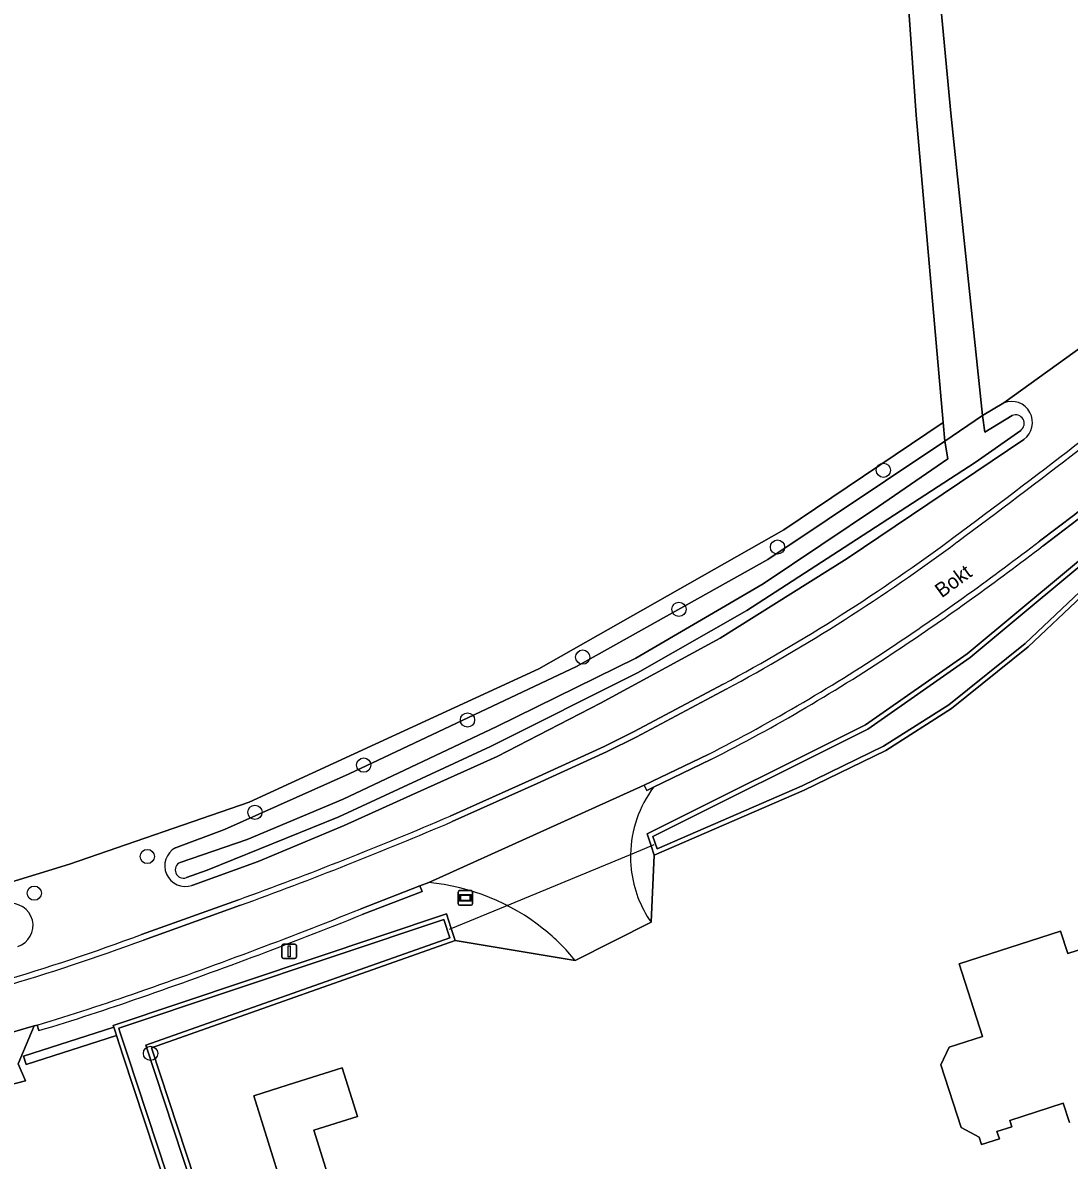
# Model space of a CAD drawing. Extents: x 162510 to 163918, y 388494 to 389774.
# Drawn here: x 163197 to 163268.7, y 388980.1 to 389058.1 of the extents above; entities that cross this region are included whole.
import ezdxf

# ---------------------------------------------------------------- set-up
doc = ezdxf.new("R2010")
doc.units = 0
for name, color, linetype in [('IMGEO_Boom', 7, 'Continuous'), ('IMGEO_Bouwland', 7, 'Continuous'), ('IMGEO_Duiker', 7, 'Continuous'), ('IMGEO_Erf', 7, 'Continuous'), ('IMGEO_Grasland_overig', 7, 'Continuous'), ('IMGEO_Groenvoorziening', 7, 'Continuous'), ('IMGEO_Haag', 7, 'Continuous'), ('IMGEO_Lichtmast', 7, 'Continuous'), ('IMGEO_Loofbos', 7, 'Continuous'), ('IMGEO_Oever', 7, 'Continuous'), ('IMGEO_Openbare_ruimte_label', 7, 'Continuous'), ('IMGEO_Pand', 7, 'Continuous'), ('IMGEO_Rijbaan_lokaal_gesloten', 7, 'Continuous'), ('IMGEO_Rijbaan_lokaal_halfverhard', 7, 'Continuous'), ('IMGEO_Rijbaan_lokaal_open', 7, 'Continuous'), ('IMGEO_Verklikker', 7, 'Continuous'), ('IMGEO_Waterloop', 7, 'Continuous')]:
    doc.layers.add(name, color=color, linetype=linetype)

msp = doc.modelspace()

# ---------------------------------------------------------------- linework, layer by layer
at = {"layer": 'IMGEO_Boom'}
for centre in [(163255.98, 389027.4), (163248.726, 389022.14), (163241.972, 389017.875), (163235.38, 389014.6), (163227.484, 389010.295), (163220.374, 389007.204), (163212.919, 389003.971), (163205.542, 389000.942), (163197.799, 388998.433), (163205.769, 388987.457)]:
    msp.add_circle(centre, 0.489, dxfattribs=at)
at = {"layer": 'IMGEO_Bouwland'}
msp.add_lwpolyline([(163255.473, 389089.062), (163223.18, 389081.542), (163199.482, 389075.574), (163185.761, 389072.18), (163174.689, 389069.454), (163173.678, 389061.095), (163170.279, 389025.019), (163167.954, 388999.891), (163167.603, 388990.424), (163200.207, 389000.418), (163212.52, 389004.669), (163232.363, 389013.797), (163249.165, 389023.322), (163260.08, 389030.662), (163258.23, 389051.717), (163256.486, 389076.515)], close=True, dxfattribs=at)
at = {"layer": 'IMGEO_Duiker'}
msp.add_lwpolyline([(163226.241, 388995.959), (163226.37, 388996.013), (163230.094, 388997.552), (163238.653, 389001.09), (163240.064, 389001.673), (163240.284, 389001.764)], dxfattribs=at)
at = {"layer": 'IMGEO_Erf'}
for points in [[(163299.678, 389102.603), (163257.727, 389091.219), (163256.916, 389090.999), (163260.609, 389051.86), (163262.76, 389031.156), (163264.225, 389032.019), (163270.263, 389036.355), (163270.353, 389036.42), (163278.738, 389042.731), (163291.024, 389052.399), (163296.992, 389058.187), (163298.476, 389059.845), (163301.365, 389063.917), (163302.714, 389067.144), (163304.217, 389072.884), (163304.823, 389078.805), (163304.577, 389084.736), (163303.423, 389090.573)], [(163219.946, 388983.139), (163216.953, 388982.202), (163217.888, 388979.215), (163214.814, 388978.252), (163212.839, 388984.559), (163215.202, 388985.299), (163218.906, 388986.459)]]:
    msp.add_lwpolyline(points, close=True, dxfattribs=at)
for points in [[(163296.588, 388975.913), (163313.192, 388984.698), (163306.1, 389006.712), (163301.392, 389010.474), (163291.734, 389007.828), (163284.723, 389009.283), (163280.491, 389028.19), (163273.806, 389023.406), (163273.26, 389022.236), (163265.908, 389015.299), (163260.651, 389011.077), (163256.153, 389008.214), (163250.555, 389005.491), (163240.278, 389001.025), (163240.061, 388996.438), (163234.852, 388993.823), (163226.643, 388995.178), (163205.829, 388987.826), (163237.905, 388890.433)], [(163224.824, 388999.162), (163224.221, 388998.928), (163224.371, 388998.557), (163220.275, 388996.969)], [(163203.899, 388987.269), (163203.43, 388988.692), (163197.255, 388986.687), (163197.07, 388987.257), (163203.242, 388989.262), (163203.208, 388989.364), (163226.042, 388997.017), (163226.37, 388996.013), (163226.643, 388995.178), (163234.852, 388993.823)], [(163268.736, 388982.712), (163268.304, 388984.049), (163264.636, 388982.863), (163264.774, 388982.435), (163263.763, 388982.108), (163263.924, 388981.611), (163262.705, 388981.217), (163262.545, 388981.714), (163261.306, 388982.375), (163259.917, 388986.672), (163260.494, 388987.873), (163262.778, 388988.611), (163261.172, 388993.581), (163268.119, 388995.826), (163268.615, 388994.295), (163272.079, 388995.415)], [(163198.123, 388989.019), (163198.002, 388989.4), (163197.788, 388989.336), (163196.707, 388986.733), (163197.209, 388985.575), (163193.741, 388984.697), (163193.48, 388985.337), (163190.473, 388987.347), (163190.578, 388986.979), (163187.117, 388986.029), (163182.303, 388984.673), (163178.332, 388983.566)], [(163220.028, 388938.344), (163203.899, 388987.269)]]:
    msp.add_lwpolyline(points, dxfattribs=at)
for centre, radius, start, end in [((163223.437, 388984.431), 14.796, 51.26004, 84.62106), ((163091.453, 389317.943), 345.861, 289.18456, 291.86791), ((163224.807, 388985.901), 12.793, 38.26036, 51.92597), ((163152.686, 389140.624), 158.268, 286.68362, 289.34251)]:
    msp.add_arc(centre, radius, start, end, dxfattribs=at)
at = {"layer": 'IMGEO_Grasland_overig'}
for points in [[(163261.728, 389014.837), (163272.067, 389023.432), (163272.685, 389022.812), (163273.26, 389022.236), (163273.806, 389023.406), (163273.582, 389023.532), (163270.321, 389025.372), (163270.16, 389025.245), (163270.413, 389024.935), (163269.328, 389024.048), (163266.93, 389022.235)], [(163240.061, 388996.438), (163240.278, 389001.025), (163240.064, 389001.673), (163239.797, 389002.485), (163254.752, 389009.953), (163261.728, 389014.837)], [(163244.158, 389007.578), (163240.235, 389005.688)]]:
    msp.add_lwpolyline(points, dxfattribs=at)
for centre, radius, start, end in [((163154.852, 389168.069), 183.926, 303.72551, 307.54335), ((163187.132, 389119.446), 125.564, 297.01082, 303.79355), ((163246.556, 389000.942), 7.904, 143.09895, 178.92819), ((163246.487, 389000.946), 7.836, 178.94748, 186.93463), ((163246.519, 389000.927), 7.865, 186.76714, 214.80258)]:
    msp.add_arc(centre, radius, start, end, dxfattribs=at)
at = {"layer": 'IMGEO_Groenvoorziening'}
msp.add_lwpolyline([(163203.43, 388988.692), (163203.361, 388988.9), (163203.242, 388989.262), (163197.07, 388987.257), (163197.255, 388986.687)], close=True, dxfattribs=at)
at = {"layer": 'IMGEO_Haag'}
msp.add_lwpolyline([(163203.43, 388988.692), (163203.361, 388988.9), (163203.242, 388989.262), (163197.07, 388987.257), (163197.255, 388986.687)], close=True, dxfattribs=at)
at = {"layer": 'IMGEO_Lichtmast'}
for p, q in [((163214.771, 388994.046), (163214.771, 388994.846)), ((163214.771, 388994.846), (163214.771, 388994.046)), ((163214.871, 388994.946), (163215.661, 388994.946)), ((163215.661, 388994.946), (163214.871, 388994.946)), ((163215.761, 388994.846), (163215.761, 388994.046)), ((163215.761, 388994.046), (163215.761, 388994.846)), ((163215.661, 388993.946), (163214.871, 388993.946)), ((163214.871, 388993.946), (163215.661, 388993.946))]:
    msp.add_line(p, q, dxfattribs=at)
msp.add_lwpolyline([(163215.191, 388994.821), (163215.341, 388994.821), (163215.341, 388994.071), (163215.191, 388994.071), (163215.191, 388994.821)], dxfattribs=at)
for centre, start, end in [((163214.871, 388994.846), 90, 180), ((163214.871, 388994.846), 90, 180), ((163215.661, 388994.846), 0, 90), ((163215.661, 388994.846), 360, 90), ((163214.871, 388994.046), 180, 270), ((163214.871, 388994.046), 180, 270), ((163215.661, 388994.046), 270, 0), ((163215.661, 388994.046), 270, 0)]:
    msp.add_arc(centre, 0.1, start, end, dxfattribs=at)
at = {"layer": 'IMGEO_Loofbos'}
for points in [[(163270.263, 389036.355), (163264.225, 389032.019)], [(163207.472, 389001.54), (163210.831, 389002.803), (163219.379, 389006.613), (163221.365, 389007.536), (163234.95, 389013.954), (163248.066, 389021.285), (163260.197, 389029.398), (163260.08, 389030.662), (163249.165, 389023.322), (163232.363, 389013.797), (163212.52, 389004.669), (163200.207, 389000.418), (163167.603, 388990.424), (163167.954, 388999.891), (163170.279, 389025.019)], [(163265.6, 389029.505), (163253.49, 389021.366), (163244.794, 389015.894), (163236.597, 389011.445), (163229.508, 389007.785), (163224.292, 389005.431), (163219.03, 389003.057), (163213.146, 389000.6), (163208.655, 388998.986), (163208.602, 388998.967)], [(163226.287, 389003.706), (163232.098, 389006.305), (163236.841, 389008.468), (163238.849, 389009.479), (163245.009, 389012.752)], [(163205.147, 388995.598), (163211.792, 388997.982)]]:
    msp.add_lwpolyline(points, dxfattribs=at)
for centre, radius, start, end in [((162908.133, 389497.572), 591.418, 306.606801, 308.623043), ((163264.753, 389030.675), 1.444, 305.89934, 111.45244), ((163184.86, 389124.633), 127.025, 298.2632, 306.71907), ((163115.529, 389262.965), 281.927, 289.96501, 293.1326), ((163208.151, 389000.304), 1.411, 118.79318, 288.62668), ((163196.213, 388996.224), 1.505, 287.39687, 100.75885), ((163153.78, 389134.015), 147.641, 286.37236, 290.35997)]:
    msp.add_arc(centre, radius, start, end, dxfattribs=at)
at = {"layer": 'IMGEO_Oever'}
for points in [[(163264.225, 389032.019), (163262.76, 389031.156), (163262.939, 389030.018), (163264.805, 389031.152)], [(163265.391, 389030.134), (163262.262, 389027.928), (163253.289, 389022.099), (163246.633, 389017.79), (163239.127, 389013.527), (163229.059, 389008.487), (163218.661, 389003.65), (163209.642, 389000), (163208.22, 388999.497)], [(163229.504, 389009.849), (163239.019, 389014.524), (163247.748, 389019.625), (163255.64, 389024.926), (163260.385, 389028.191), (163260.197, 389029.398), (163248.066, 389021.285), (163234.95, 389013.954), (163221.365, 389007.536), (163219.379, 389006.613), (163210.831, 389002.803), (163207.472, 389001.54)], [(163208.602, 388998.967), (163208.655, 388998.986), (163213.146, 389000.6), (163219.03, 389003.057), (163224.292, 389005.431), (163229.508, 389007.785), (163236.597, 389011.445), (163244.794, 389015.894), (163253.49, 389021.366), (163265.6, 389029.505)], [(163207.807, 389000.543), (163212.384, 389002.113), (163218.964, 389004.875), (163229.504, 389009.849)], [(163205.829, 388987.826), (163226.643, 388995.178), (163226.37, 388996.013), (163226.042, 388997.017), (163203.208, 388989.364), (163203.242, 388989.262), (163203.361, 388988.9), (163203.43, 388988.692), (163203.899, 388987.269), (163220.028, 388938.344), (163223.616, 388927.461), (163236.766, 388888.053), (163294.567, 388906.947), (163302.097, 388885.506), (163302.403, 388884.634), (163389.097, 388910.154)], [(163204.183, 388987.363), (163203.645, 388988.993), (163203.586, 388989.175), (163225.851, 388996.637), (163226.268, 388995.363), (163205.453, 388988.011), (163237.714, 388890.055), (163295.698, 388909.171), (163303.452, 388886.507), (163348.836, 388899.935), (163350.219, 388900.446), (163351.114, 388900.684), (163388.413, 388911.451), (163389.08, 388915.215), (163389.499, 388916.535)], [(163389.001, 388910.438), (163302.591, 388885.001), (163302.379, 388885.605), (163294.752, 388907.322), (163236.956, 388888.43), (163223.9, 388927.555), (163220.312, 388938.438), (163204.183, 388987.363)], [(163389.217, 388916.637), (163388.789, 388915.287), (163388.151, 388911.687), (163362.046, 388904.151), (163360.59, 388903.731), (163351.034, 388900.972), (163350.129, 388900.732), (163348.742, 388900.219), (163303.642, 388886.875), (163295.885, 388909.548), (163237.905, 388890.433), (163205.829, 388987.826)]]:
    msp.add_lwpolyline(points, dxfattribs=at)
for points in [[(163256.153, 389008.214), (163260.651, 389011.077), (163265.908, 389015.299), (163273.26, 389022.236), (163272.685, 389022.812), (163272.067, 389023.432), (163261.728, 389014.837), (163254.752, 389009.953), (163239.797, 389002.485), (163240.064, 389001.673), (163240.278, 389001.025), (163250.555, 389005.491)], [(163272.456, 389022.584), (163272.796, 389022.243), (163265.696, 389015.543), (163260.462, 389011.34), (163255.995, 389008.497), (163250.42, 389005.785), (163240.474, 389001.462), (163240.191, 389002.321), (163254.918, 389009.675), (163261.924, 389014.58), (163272.047, 389022.995)]]:
    msp.add_lwpolyline(points, close=True, dxfattribs=at)
for centre, radius, start, end in [((163264.753, 389030.675), 1.444, 305.89934, 111.45244), ((163265.034, 389030.606), 0.592, 307.04878, 112.804), ((163208.151, 389000.304), 1.411, 118.79318, 288.62668), ((163208.02, 389000.023), 0.562, 112.24936, 290.84257), ((163196.213, 388996.224), 1.505, 287.39687, 100.75885)]:
    msp.add_arc(centre, radius, start, end, dxfattribs=at)
at = {"layer": 'IMGEO_Pand'}
msp.add_lwpolyline([(163272.079, 388995.415), (163268.615, 388994.295), (163268.119, 388995.826), (163261.172, 388993.581), (163262.778, 388988.611), (163260.494, 388987.873), (163259.917, 388986.672), (163261.306, 388982.375), (163262.545, 388981.714), (163262.705, 388981.217), (163263.924, 388981.611), (163263.763, 388982.108), (163264.774, 388982.435), (163264.636, 388982.863), (163268.304, 388984.049), (163268.736, 388982.712)], dxfattribs=at)
msp.add_lwpolyline([(163212.839, 388984.559), (163214.814, 388978.252), (163217.888, 388979.215), (163216.953, 388982.202), (163219.946, 388983.139), (163218.906, 388986.459), (163215.202, 388985.299)], close=True, dxfattribs=at)
at = {"layer": 'IMGEO_Rijbaan_lokaal_gesloten'}
for points in [[(163266.686, 389022.552), (163269.087, 389024.367), (163270.16, 389025.245), (163270.321, 389025.372), (163280.513, 389033.412), (163285.735, 389037.648)], [(163245.197, 389012.399), (163239.029, 389009.122), (163237.007, 389008.104), (163232.261, 389005.94), (163226.444, 389003.338)], [(163220.126, 388997.34), (163224.221, 388998.928), (163224.824, 388999.162), (163239.596, 389005.824), (163243.976, 389007.934)], [(163240.235, 389005.688), (163239.77, 389005.464), (163239.596, 389005.824), (163224.824, 388999.162)], [(163211.927, 388997.605), (163205.286, 388995.223)], [(163234.852, 388993.823), (163240.061, 388996.438)], [(163178.219, 388983.931), (163182.23, 388985.017), (163187.003, 388986.355), (163190.473, 388987.347), (163191.057, 388987.377), (163197.788, 388989.336), (163198.002, 388989.4)]]:
    msp.add_lwpolyline(points, dxfattribs=at)
for centre, radius, start, end in [((162905.811, 389500.603), 595.636, 306.61225, 308.61552), ((163184.796, 389124.736), 127.546, 298.2657, 306.7141), ((163154.672, 389168.303), 183.822, 303.73151, 307.54322), ((163186.834, 389119.961), 125.759, 297.02495, 303.77589), ((163246.556, 389000.942), 7.904, 143.09895, 178.92819), ((163115.637, 389262.675), 282.018, 289.96418, 293.13557), ((163246.487, 389000.946), 7.836, 178.94748, 186.93463), ((163246.519, 389000.927), 7.865, 186.76714, 214.80258), ((163223.437, 388984.431), 14.796, 51.26004, 84.62106), ((163091.949, 389316.672), 344.097, 289.17646, 291.87013), ((163224.807, 388985.901), 12.793, 38.26036, 51.92597), ((163153.605, 389134.532), 148.586, 286.38228, 290.3539), ((163153.101, 389139.283), 156.464, 286.67686, 289.36304)]:
    msp.add_arc(centre, radius, start, end, dxfattribs=at)
at = {"layer": 'IMGEO_Rijbaan_lokaal_halfverhard'}
for points in [[(163270.16, 389025.245), (163269.087, 389024.367), (163266.686, 389022.552)], [(163266.93, 389022.235), (163269.328, 389024.048), (163270.413, 389024.935), (163270.16, 389025.245)], [(163245.009, 389012.752), (163238.849, 389009.479), (163236.841, 389008.468), (163232.098, 389006.305), (163226.287, 389003.706)], [(163226.444, 389003.338), (163232.261, 389005.94), (163237.007, 389008.104), (163239.029, 389009.122), (163245.197, 389012.399)], [(163243.976, 389007.934), (163239.596, 389005.824), (163239.77, 389005.464), (163240.235, 389005.688), (163244.158, 389007.578)], [(163224.221, 388998.928), (163220.126, 388997.34)], [(163220.275, 388996.969), (163224.371, 388998.557), (163224.221, 388998.928)], [(163211.792, 388997.982), (163205.147, 388995.598)], [(163205.286, 388995.223), (163211.927, 388997.605)], [(163198.002, 388989.4), (163198.123, 388989.019)]]:
    msp.add_lwpolyline(points, dxfattribs=at)
for centre, radius, start, end in [((162908.133, 389497.572), 591.418, 306.606801, 308.623043), ((162905.811, 389500.603), 595.636, 306.61225, 308.61552), ((163184.86, 389124.633), 127.025, 298.2632, 306.71907), ((163184.796, 389124.736), 127.546, 298.2657, 306.7141), ((163154.672, 389168.303), 183.822, 303.73151, 307.54322), ((163154.852, 389168.069), 183.926, 303.72551, 307.54335), ((163186.834, 389119.961), 125.759, 297.02495, 303.77589), ((163187.132, 389119.446), 125.564, 297.01082, 303.79355), ((163115.529, 389262.965), 281.927, 289.96501, 293.1326), ((163115.637, 389262.675), 282.018, 289.96418, 293.13557), ((163091.949, 389316.672), 344.097, 289.17646, 291.87013), ((163091.453, 389317.943), 345.861, 289.18456, 291.86791), ((163153.78, 389134.015), 147.641, 286.37236, 290.35997), ((163153.605, 389134.532), 148.586, 286.38228, 290.3539), ((163153.101, 389139.283), 156.464, 286.67686, 289.36304), ((163152.686, 389140.624), 158.268, 286.68362, 289.34251)]:
    msp.add_arc(centre, radius, start, end, dxfattribs=at)
at = {"layer": 'IMGEO_Rijbaan_lokaal_open'}
msp.add_lwpolyline([(163196.707, 388986.733), (163197.788, 388989.336), (163191.057, 388987.377), (163190.473, 388987.347), (163193.48, 388985.337), (163193.741, 388984.697), (163197.209, 388985.575)], close=True, dxfattribs=at)
at = {"layer": 'IMGEO_Verklikker'}
for p, q in [((163226.835, 388997.708), (163226.835, 388998.508)), ((163226.835, 388998.508), (163226.835, 388997.708)), ((163226.935, 388998.608), (163227.725, 388998.608)), ((163227.725, 388998.608), (163226.935, 388998.608)), ((163227.825, 388998.508), (163227.825, 388997.708)), ((163227.825, 388997.708), (163227.825, 388998.508)), ((163227.725, 388997.608), (163226.935, 388997.608)), ((163226.935, 388997.608), (163227.725, 388997.608))]:
    msp.add_line(p, q, dxfattribs=at)
for points in [[(163226.936, 388998.34), (163227.724, 388998.34), (163227.724, 388997.876), (163226.936, 388997.876), (163226.936, 388998.34)], [(163227.001, 388998.275), (163227.001, 388997.941), (163227.659, 388997.941), (163227.659, 388998.275), (163227.001, 388998.275)]]:
    msp.add_lwpolyline(points, dxfattribs=at)
for centre, start, end in [((163226.935, 388998.508), 90, 180), ((163226.935, 388998.508), 90, 180), ((163227.725, 388998.508), 0, 90), ((163227.725, 388998.508), 360, 90), ((163226.935, 388997.708), 180, 270), ((163226.935, 388997.708), 180, 270), ((163227.725, 388997.708), 270, 0), ((163227.725, 388997.708), 270, 0)]:
    msp.add_arc(centre, 0.1, start, end, dxfattribs=at)
at = {"layer": 'IMGEO_Waterloop'}
for points in [[(163256.486, 389076.515), (163258.23, 389051.717), (163260.08, 389030.662), (163260.197, 389029.398), (163262.76, 389031.156), (163260.609, 389051.86), (163256.916, 389090.999)], [(163264.805, 389031.152), (163262.939, 389030.018), (163262.76, 389031.156), (163260.197, 389029.398), (163260.385, 389028.191), (163255.64, 389024.926), (163247.748, 389019.625), (163239.019, 389014.524), (163229.504, 389009.849), (163218.964, 389004.875), (163212.384, 389002.113), (163207.807, 389000.543)], [(163262.262, 389027.928), (163265.391, 389030.134)], [(163208.22, 388999.497), (163209.642, 389000), (163218.661, 389003.65), (163229.059, 389008.487), (163239.127, 389013.527), (163246.633, 389017.79), (163253.289, 389022.099), (163262.262, 389027.928)], [(163389.499, 388916.535), (163389.08, 388915.215), (163388.413, 388911.451), (163351.114, 388900.684), (163350.219, 388900.446), (163348.836, 388899.935), (163303.452, 388886.507), (163295.698, 388909.171), (163237.714, 388890.055), (163205.453, 388988.011), (163226.268, 388995.363), (163225.851, 388996.637), (163203.586, 388989.175), (163203.645, 388988.993), (163204.183, 388987.363), (163220.312, 388938.438), (163223.9, 388927.555), (163236.956, 388888.43), (163294.752, 388907.322), (163302.379, 388885.605), (163302.591, 388885.001), (163389.001, 388910.438)]]:
    msp.add_lwpolyline(points, dxfattribs=at)
msp.add_lwpolyline([(163272.456, 389022.584), (163272.047, 389022.995), (163261.924, 389014.58), (163254.918, 389009.675), (163240.191, 389002.321), (163240.474, 389001.462), (163250.42, 389005.785), (163255.995, 389008.497), (163260.462, 389011.34), (163265.696, 389015.543), (163272.796, 389022.243)], close=True, dxfattribs=at)
for centre, radius, start, end in [((163265.034, 389030.606), 0.592, 307.04878, 112.804), ((163208.02, 389000.023), 0.562, 112.24936, 290.84257)]:
    msp.add_arc(centre, radius, start, end, dxfattribs=at)

# ---------------------------------------------------------------- texts
at = {"layer": 'IMGEO_Openbare_ruimte_label'}
msp.add_text('Bokt', height=1, rotation=36.25076, dxfattribs=at).set_placement((163259.976, 389018.621))

doc.saveas('drawing.dxf')
